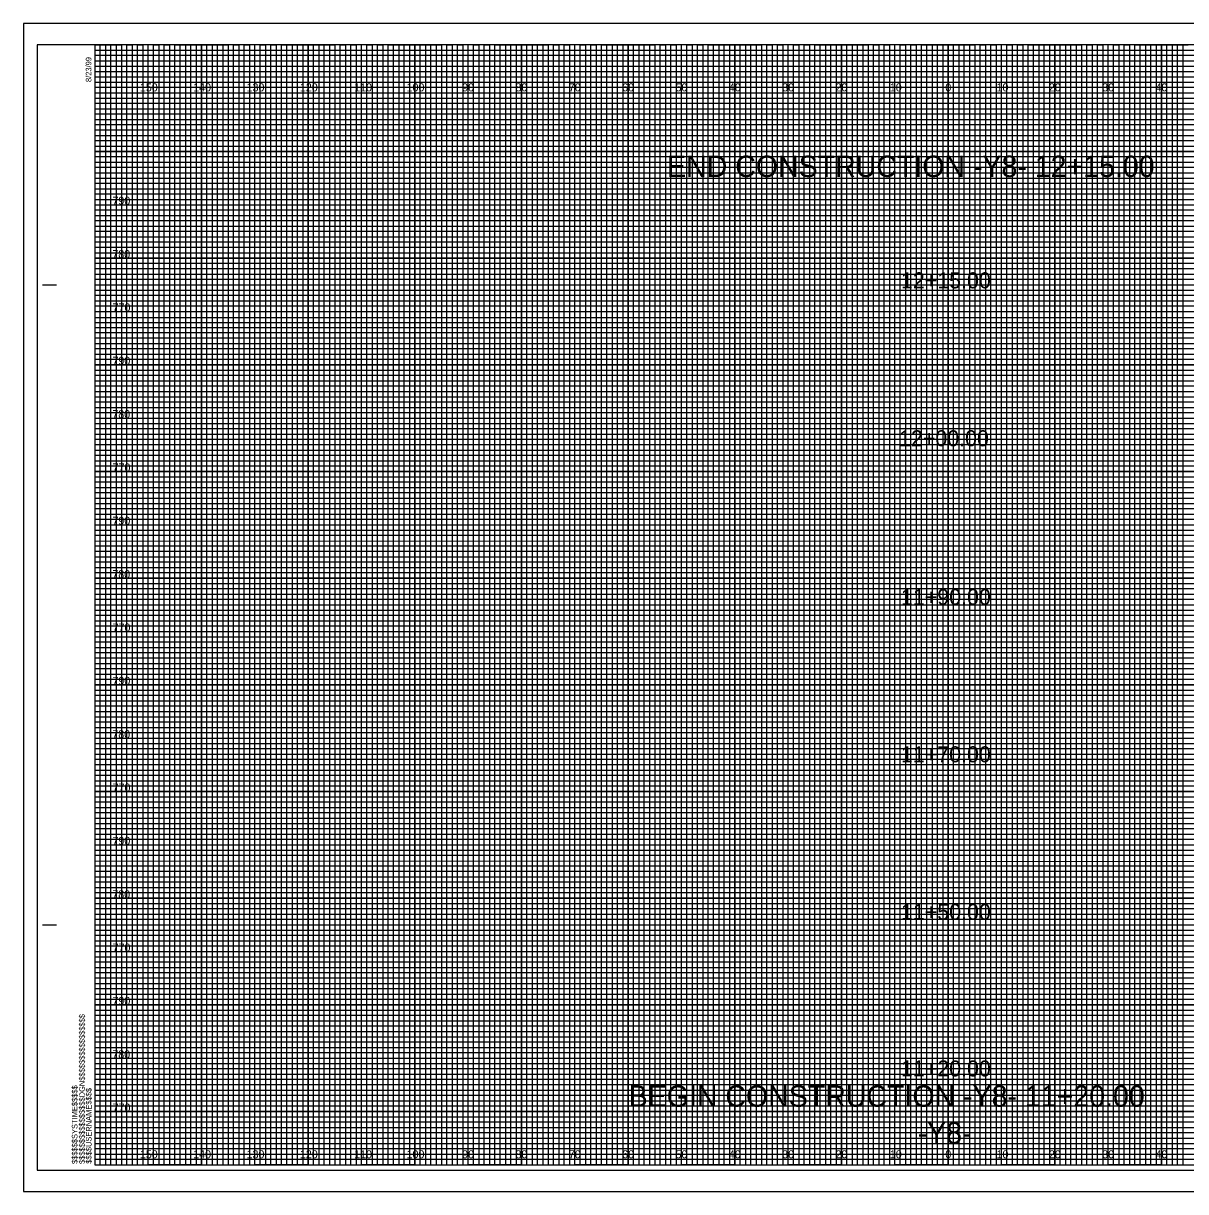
# Model space of a CAD drawing. Extents: x -13 to 323, y -5 to 214.
# Drawn here: x -13.4 to 204.5, y -5 to 214 of the extents above; entities that cross this region are included whole.
import ezdxf

# ---------------------------------------------------------------- set-up
doc = ezdxf.new("R2010")
doc.units = 0
for name, color, linetype in [('Prop XS Alignment Label', 7, 'Continuous'), ('Prop XS Elevation Labels', 7, 'Continuous'), ('Prop XS Offset Labels', 7, 'Continuous'), ('Prop XS Station Labels', 7, 'Continuous'), ('Sheet Cross Section CELL', 7, 'Continuous'), ('Sheet Cross Section Grid Major CELL', 7, 'Continuous'), ('Sheet Cross Section Grid Middle CELL', 7, 'Continuous'), ('Sheet Cross Section Grid Minor 1 CELL', 7, 'Continuous'), ('Sheet Cross Section Grid Minor 2 CELL', 7, 'Continuous'), ('Sheet Cutting Line CELL', 7, 'Continuous'), ('Sheet DOT Grid CELL', 7, 'Continuous'), ('Sheet Plot Border Inside CELL', 7, 'Continuous'), ('Sheet Plot Border Outside CELL', 7, 'Continuous')]:
    doc.layers.add(name, color=color, linetype=linetype)

msp = doc.modelspace()

# ---------------------------------------------------------------- linework, layer by layer
at = {"layer": 'Sheet Cross Section CELL'}
for p, q in [((-9.8, 165), (-7.3, 165)), ((-9.7, 165), (-7.2, 165)), ((-9.8, 45), (-7.3, 45)), ((-9.7, 45), (-7.2, 45)), ((0, 0), (0, 0)), ((0, 0), (0, 0)), ((0, 0), (0, 0)), ((0, 0), (0, 0)), ((0, 0), (0, 0)), ((0, 0), (0, 0)), ((0, 0), (0, 0))]:
    msp.add_line(p, q, dxfattribs=at)
msp.add_lwpolyline([(320, 210), (0, 210), (0, 0), (320, 0)], close=True, dxfattribs=at)
at = {"layer": 'Sheet Cross Section Grid Major CELL'}
for p, q in [((10, 210), (0, 210)), ((10, 0), (10, 210)), ((30, 210), (20, 210)), ((20, 210), (20, 0)), ((30, 0), (30, 210)), ((50, 210), (40, 210)), ((40, 210), (40, 0)), ((50, 0), (50, 210)), ((70, 210), (60, 210)), ((60, 210), (60, 0)), ((70, 0), (70, 210)), ((90, 210), (80, 210)), ((80, 210), (80, 0)), ((90, 0), (90, 210)), ((110, 210), (100, 210)), ((100, 210), (100, 0)), ((110, 0), (110, 210)), ((130, 210), (120, 210)), ((120, 210), (120, 0)), ((130, 0), (130, 210)), ((150, 210), (140, 210)), ((140, 210), (140, 0)), ((150, 0), (150, 210)), ((170, 210), (160, 210)), ((160, 210), (160, 0)), ((170, 0), (170, 210)), ((190, 210), (180, 210)), ((180, 210), (180, 0)), ((190, 0), (190, 210)), ((210, 210), (200, 210)), ((200, 210), (200, 0)), ((20, 0), (10, 0)), ((40, 0), (30, 0)), ((60, 0), (50, 0)), ((80, 0), (70, 0)), ((100, 0), (90, 0)), ((120, 0), (110, 0)), ((140, 0), (130, 0)), ((160, 0), (150, 0)), ((180, 0), (170, 0)), ((200, 0), (190, 0))]:
    msp.add_line(p, q, dxfattribs=at)
for points in [[(0, 200), (320, 200), (320, 190), (0, 190)], [(0, 180), (320, 180), (320, 170), (0, 170)], [(0, 160), (320, 160), (320, 150), (0, 150)], [(0, 140), (320, 140), (320, 130), (0, 130)], [(0, 120), (320, 120), (320, 110), (0, 110)], [(0, 100), (320, 100), (320, 90), (0, 90)], [(0, 80), (320, 80), (320, 70), (0, 70)], [(0, 60), (320, 60), (320, 50), (0, 50)], [(0, 40), (320, 40), (320, 30), (0, 30)], [(0, 20), (320, 20), (320, 10), (0, 10)]]:
    msp.add_lwpolyline(points, dxfattribs=at)
at = {"layer": 'Sheet Cross Section Grid Middle CELL'}
for points in [[(0, 210), (5, 210), (5, 0), (15, 0), (15, 210), (25, 210), (25, 0), (35, 0), (35, 210), (45, 210), (45, 0), (55, 0), (55, 210), (65, 210), (65, 0), (75, 0), (75, 210), (85, 210), (85, 0), (95, 0), (95, 210), (105, 210), (105, 0), (115, 0), (115, 210), (125, 210), (125, 0), (135, 0), (135, 210), (145, 210), (145, 0), (155, 0), (155, 210), (165, 210), (165, 0), (175, 0), (175, 210), (185, 210), (185, 0), (195, 0), (195, 210), (205, 210)], [(0, 205), (275, 205)], [(0, 185), (320, 185), (320, 195), (0, 195)], [(0, 165), (320, 165), (320, 175), (0, 175)], [(0, 145), (320, 145), (320, 155), (0, 155)], [(0, 125), (320, 125), (320, 135), (0, 135)], [(0, 105), (320, 105), (320, 115), (0, 115)], [(0, 85), (320, 85), (320, 95), (0, 95)], [(0, 65), (320, 65), (320, 75), (0, 75)], [(0, 45), (320, 45), (320, 55), (0, 55)], [(0, 25), (320, 25), (320, 35), (0, 35)], [(0, 5), (320, 5), (320, 15), (0, 15)]]:
    msp.add_lwpolyline(points, dxfattribs=at)
at = {"layer": 'Sheet Cross Section Grid Minor 1 CELL'}
for p, q in [((0, 209), (260, 209)), ((260, 207.98), (0, 207.98)), ((0, 207.98), (0, 207)), ((0, 207), (260, 207)), ((260, 205.89), (0, 205.89)), ((0, 205.89), (0, 204)), ((0, 204), (320, 204))]:
    msp.add_line(p, q, dxfattribs=at)
for points in [[(0, 203), (270, 203), (320, 203), (320, 202), (0, 202)], [(0, 201), (320, 201), (320, 199), (0, 199)], [(0, 198), (320, 198), (320, 197), (0, 196.98)], [(0, 196), (320, 196), (320, 194), (0, 194)], [(0, 193), (320, 193), (320, 192), (0, 192)], [(0, 191), (320, 191), (320, 189), (0, 189)], [(0, 188), (320, 188), (320, 187), (0, 187)], [(0, 186), (320, 186), (320, 184), (0, 184)], [(0, 183), (320, 183), (320, 182), (0, 182)], [(0, 181), (320, 181), (320, 179), (0, 179)], [(0, 178), (320, 178), (320, 177), (0, 177)], [(0, 176), (320, 176), (320, 173.95), (320, 173), (320, 172), (0, 172)], [(0, 174), (320, 174), (320, 173), (0, 173)], [(0, 171), (320, 171), (320, 169), (0, 169.03)], [(0, 169.03), (320, 169), (320, 168), (0, 168)], [(0, 167), (320, 167), (320, 166), (0, 166)], [(0, 164), (320, 164), (320, 163), (0, 163)], [(0, 162), (320, 162), (320, 161), (0, 161)], [(-0.07, 158.89), (320, 158.89), (320, 157.88), (-0.07, 157.88)], [(0, 157), (320, 157), (320, 156), (0, 156)], [(0, 154), (320, 154), (320, 153), (0, 153)], [(0, 152), (320, 152), (320, 151), (0, 151)], [(0, 149), (320, 149), (320, 148), (0, 148)], [(0, 147), (320, 147), (320, 146), (0, 146)], [(0, 144), (320, 144), (320, 143), (0, 143)], [(0, 142), (320, 142), (320, 141), (0, 141)], [(0, 139), (320, 139), (319.99, 137.98), (0, 138)], [(0, 137), (320, 137), (320, 136), (0, 136)], [(0, 134), (320, 134), (320, 133), (0, 133)], [(0, 132), (320, 132), (320, 131), (0, 131)], [(0, 129), (320, 129), (320, 128), (0, 128)], [(0, 127), (320, 127), (320, 126), (0, 126)], [(0, 124), (320, 124), (320, 123), (0, 123)], [(0, 122), (320, 122), (320, 121), (0, 121)], [(0, 119), (320, 119), (320, 118), (0, 118)], [(0, 116.99), (320.07, 116.91), (320, 116), (0, 116)], [(0, 114), (320, 114), (320, 113), (0, 113)], [(0, 112), (320, 112), (320, 111), (0, 111)], [(0, 109), (320, 109), (320, 108), (0, 108)], [(0, 107), (320, 107), (320, 106), (0, 106)], [(0, 104), (320, 104), (320, 103), (0, 103)], [(0, 102), (320, 102), (320, 101), (0, 101)], [(0, 99), (320, 99), (320, 98), (0, 98)], [(0, 97), (320, 97), (320, 96), (0, 96)], [(0, 94), (320, 94), (320, 93), (0, 93)], [(0, 92), (320, 92), (320, 91), (0, 91)], [(0, 89), (320, 89), (320, 88), (0, 88)], [(0, 87), (320, 87), (320, 86), (0, 86)], [(0, 84), (320, 84), (320, 83), (0, 83)], [(0, 82), (320, 82), (320, 81), (0, 81)], [(0, 79), (320, 79), (319.99, 77.98), (0, 78)], [(0, 77), (320, 77), (320, 76), (0, 76)], [(0, 74), (320, 74), (320, 73), (0, 73)], [(0, 72), (320, 72), (320, 71), (0, 71)], [(0, 69), (320, 69), (320, 68), (0, 68)], [(0, 67), (320, 67), (320, 66), (0, 66)], [(0, 64), (320, 64), (320, 63), (0, 63)], [(0, 62), (320, 62), (320, 61), (0, 61)], [(0, 59), (320, 59), (320, 58), (0, 58)], [(0, 56.99), (320.07, 56.91), (320, 56), (0, 56)], [(0, 54), (320, 54), (320, 53), (0, 53)], [(0, 52), (320, 52), (320, 51), (0, 51)], [(0, 49), (320, 49), (320, 48), (0, 48)], [(0, 47), (320, 47), (320, 46), (0, 46)], [(0, 44), (320, 44), (320, 43), (0, 43)], [(0, 42), (320, 42), (320, 41), (0, 41)], [(0, 39), (320, 39), (320, 38), (0, 38)], [(0, 37), (320, 37), (320, 36), (0, 36)], [(0, 34), (320, 34), (320, 33), (0, 33)], [(0, 32), (320, 32), (320, 31), (0, 31)], [(0, 29), (320, 29), (320, 28), (0, 28)], [(0, 27), (320, 27), (320, 26), (0, 26)], [(0, 24), (320, 24), (320, 23), (0, 23)], [(0, 22), (320, 22), (320, 21), (0, 21)], [(0, 19), (320, 19), (320, 18), (0, 18)], [(0, 17), (320, 17), (320, 16), (0, 16)], [(0, 14), (320, 14), (320, 13), (0, 13)], [(0, 12), (320, 12), (320, 11), (0, 11)], [(0, 9), (320, 9), (320, 8), (0, 8)], [(0, 7), (320, 7), (320, 6), (0, 6)], [(0, 4), (320, 4), (320, 3), (0, 3)], [(0, 2), (320, 2), (320, 1), (0, 1)]]:
    msp.add_lwpolyline(points, dxfattribs=at)
at = {"layer": 'Sheet Cross Section Grid Minor 2 CELL'}
for points in [[(0, 0), (1, 0), (1, 210), (2, 210), (2, 0)], [(2, 0), (3, 0), (3, 210), (4, 210), (4, 0)], [(5, 0), (6, 0), (6, 210), (7, 210), (7, 0)], [(7, 0), (8, 0), (8, 210), (9, 210), (9, 0)], [(10, 0), (11, 0), (11, 210), (12, 210), (12, 0)], [(12, 0), (13, 0), (13, 210), (14, 210), (14, 0)], [(15, 0), (16, 0), (16, 210), (17, 210), (17, 0)], [(17, 0), (18, 0), (18, 210), (19, 210), (19, 0)], [(20, 0), (21, 0), (21, 210), (22, 210), (22, 0)], [(22, 0), (23, 0), (23, 210), (24, 210), (24, 0)], [(25, 0), (26, 0), (26, 210), (27, 210), (27, 0)], [(27, 0), (28, 0), (28, 210), (29, 210), (29, 0)], [(30, 0), (31, 0), (31, 210), (32, 210), (32, 0)], [(32, 0), (33, 0), (33, 210), (34, 210), (34, 0)], [(35, 0), (36, 0), (36, 210), (37, 210), (37, 0)], [(37, 0), (38, 0), (38, 210), (39, 210), (39, 0)], [(40, 0), (41, 0), (41, 210), (42, 210), (42, 0)], [(42, 0), (43, 0), (43, 210), (44, 210), (44, 0)], [(45, 0), (46, 0), (46, 210), (47, 210), (47, 0)], [(47, 0), (48, 0), (48, 210), (49, 210), (49, 0)], [(50, 0), (51, 0), (51, 210), (52, 210), (52, 0)], [(52, 0), (53, 0), (53, 210), (54, 210), (54, 0)], [(55, 0), (56, 0), (56, 210), (57, 210), (57, 0)], [(57, 0), (58, 0), (58, 210), (59, 210), (59, 0)], [(60, 0), (61, 0), (61, 210), (62, 210), (62, 0)], [(62, 0), (63, 0), (63, 210), (64, 210), (64, 0)], [(65, 0), (66, 0), (66, 210), (67, 210), (67, 0)], [(67, 0), (68, 0), (68, 210), (69, 210), (69, 0)], [(70, 0), (71, 0), (71, 210), (72, 210), (72, 0)], [(72, 0), (73, 0), (73, 210), (74, 210), (74, 0)], [(75, 0), (76, 0), (76, 210), (77, 210), (77, 0)], [(77, 0), (78, 0), (78, 210), (79, 210), (79, 0)], [(80, 0), (81, 0), (81, 210), (82, 210), (82, 0)], [(82, 0), (83, 0), (83, 210), (84, 210), (84, 0)], [(85, 0), (86, 0), (86, 210), (87, 210), (87, 0)], [(87, 0), (88, 0), (88, 210), (89, 210), (89, 0)], [(90, 0), (91, 0), (91, 210), (92, 210), (92, 0)], [(92, 0), (93, 0), (93, 210), (94, 210), (94, 0)], [(95, 0), (96, 0), (96, 210), (97, 210), (97, 0)], [(97, 0), (98, 0), (98, 210), (99, 210), (99, 0)], [(100, 0), (101, 0), (101, 210), (102, 210), (102, 0)], [(102, 0), (103, 0), (103, 210), (104, 210), (104, 0)], [(105, 0), (106, 0), (106, 210), (107, 210), (107, 0)], [(107, 0), (108, 0), (108, 210), (109, 210), (109, 0)], [(110, 0), (111, 0), (111, 210), (112, 210), (112, 0)], [(112, 0), (113, 0), (113, 210), (114, 210), (114, 0)], [(115, 0), (116, 0), (116, 210), (117, 210), (117, 0)], [(117, 0), (118, 0), (118, 210), (119, 210), (119, 0)], [(120, 0), (121, 0), (121, 210), (122, 210), (122, 0)], [(122, 0), (123, 0), (123, 210), (124, 210), (124, 0)], [(125, 0), (126, 0), (126, 210), (127, 210), (127, 0)], [(127, 0), (128, 0), (128, 210), (129, 210), (129, 0)], [(130, 0), (131, 0), (131, 210), (132, 210), (132, 0)], [(132, 0), (133, 0), (133, 210), (134, 210), (134, 0)], [(135, 0), (136, 0), (136, 210), (137, 210), (137, 0)], [(137, 0), (138, 0), (138, 210), (139, 210), (139, 0)], [(140, 0), (141, 0), (141, 210), (142, 210), (142, 0)], [(142, 0), (143, 0), (143, 210), (144, 210), (144, 0)], [(145, 0), (146, 0), (146, 210), (147, 210), (147, 0)], [(147, 0), (148, 0), (148, 210), (149, 210), (149, 0)], [(150, 0), (151, 0), (151, 210), (152, 210), (152, 0)], [(152, 0), (153, 0), (153, 210), (154, 210), (154, 0)], [(155, 0), (156, 0), (156, 210), (157, 210), (157, 0)], [(157, 0), (158, 0), (158, 210), (159, 210), (159, 0)], [(160, 0), (161, 0), (161, 210), (162, 210), (162, 0)], [(162, 0), (163, 0), (163, 210), (164, 210), (164, 0)], [(165, 0), (166, 0), (166, 210), (167, 210), (167, 0)], [(167, 0), (168, 0), (168, 210), (169, 210), (169, 0)], [(170, 0), (171, 0), (171, 210), (172, 210), (172, 0)], [(172, 0), (173, 0), (173, 210), (174, 210), (174, 0)], [(175, 0), (176, 0), (176, 210), (177, 210), (177, 0)], [(177, 0), (178, 0), (178, 210), (179, 210), (179, 0)], [(180, 0), (181, 0), (181, 210), (182, 210), (182, 0)], [(182, 0), (183, 0), (183, 210), (184, 210), (184, 0)], [(185, 0), (186, 0), (186, 210), (187, 210), (187, 0)], [(187, 0), (188, 0), (188, 210), (189, 210), (189, 0)], [(190, 0), (191, 0), (191, 210), (192, 210), (192, 0)], [(192, 0), (193, 0), (193, 210), (194, 210), (194, 0)], [(195, 0), (196, 0), (196, 210), (197, 210), (197, 0)], [(197, 0), (198, 0), (198, 210), (199, 210), (199, 0)], [(200, 0), (201, 0), (201, 210), (202, 210), (202, 0)], [(202, 0), (203, 0), (203, 210), (204, 210), (204, 0)]]:
    msp.add_lwpolyline(points, dxfattribs=at)
at = {"layer": 'Sheet Cutting Line CELL'}
for p, q in [((323.3, 214), (-13.4, 214)), ((-13.4, 214), (-13.4, -5)), ((-13.4, -5), (323.3, -5))]:
    msp.add_line(p, q, dxfattribs=at)
at = {"layer": 'Sheet DOT Grid CELL'}
for p, q in [((10, 0), (10, 210)), ((20, 0), (20, 210)), ((30, 0), (30, 210)), ((40, 0), (40, 210)), ((50, 0), (50, 210)), ((60, 0), (60, 210)), ((70, 0), (70, 210)), ((80, 0), (80, 210)), ((90, 0), (90, 210)), ((100, 0), (100, 210)), ((110, 0), (110, 210)), ((120, 0), (120, 210)), ((130, 0), (130, 210)), ((140, 0), (140, 210)), ((150, 0), (150, 210)), ((160, 0), (160, 210)), ((170, 0), (170, 210)), ((180, 0), (180, 210)), ((190, 0), (190, 210)), ((200, 0), (200, 210)), ((0, 200), (320, 200)), ((0, 190), (320, 190)), ((0, 180), (320, 180)), ((0, 170), (320, 170)), ((0, 160), (320, 160)), ((0, 150), (320, 150)), ((0, 140), (320, 140)), ((0, 130), (320, 130)), ((0, 120), (320, 120)), ((0, 110), (320, 110)), ((0, 100), (320, 100)), ((0, 90), (320, 90)), ((0, 80), (320, 80)), ((0, 70), (320, 70)), ((0, 60), (320, 60)), ((0, 50), (320, 50)), ((0, 40), (320, 40)), ((0, 30), (320, 30)), ((0, 20), (320, 20)), ((0, 10), (320, 10))]:
    msp.add_line(p, q, dxfattribs=at)
at = {"layer": 'Sheet Plot Border Inside CELL'}
msp.add_lwpolyline([(-10.8, -1), (322.4, -1), (322.4, 210), (-10.8, 210)], close=True, dxfattribs=at)
at = {"layer": 'Sheet Plot Border Outside CELL'}
msp.add_lwpolyline([(-13.4, -5), (323.3, -5), (323.3, 214), (-13.4, 214)], close=True, dxfattribs=at)

# ---------------------------------------------------------------- texts
at = {"layer": 'Prop XS Alignment Label'}
for s, p in [('END CONSTRUCTION -Y8- 12+15.00', (107.28, 185.2)), ('BEGIN CONSTRUCTION -Y8- 11+20.00', (100.08, 10.91)), ('-Y8-', (154.25, 4))]:
    msp.add_text(s, height=4, dxfattribs=at).set_placement(p)
at = {"layer": 'Prop XS Elevation Labels'}
for s, p in [('790', (3.3, 180)), ('780', (3.28, 170)), ('770', (3.33, 160)), ('790', (3.3, 150)), ('780', (3.28, 140)), ('770', (3.33, 130)), ('790', (3.3, 120)), ('780', (3.28, 110)), ('770', (3.33, 100)), ('790', (3.3, 90)), ('780', (3.28, 80)), ('770', (3.33, 70)), ('790', (3.3, 60)), ('780', (3.28, 50)), ('770', (3.33, 40)), ('790', (3.3, 30)), ('780', (3.28, 20)), ('770', (3.33, 10))]:
    msp.add_text(s, height=1.5, dxfattribs=at).set_placement(p)
at = {"layer": 'Prop XS Offset Labels'}
for s, p in [('150', (8.44, 201.25)), ('140', (18.44, 201.25)), ('130', (28.44, 201.25)), ('120', (38.44, 201.25)), ('110', (48.62, 201.25)), ('100', (58.44, 201.25)), ('90', (68.86, 201.25)), ('80', (78.86, 201.25)), ('70', (88.86, 201.25)), ('60', (98.86, 201.25)), ('50', (108.86, 201.25)), ('40', (118.86, 201.25)), ('30', (128.86, 201.25)), ('20', (138.86, 201.25)), ('10', (149.04, 201.25)), ('0', (159.45, 201.25)), ('0', (159.45, 201.25)), ('10', (169.04, 201.25)), ('20', (178.86, 201.25)), ('30', (188.86, 201.25)), ('40', (198.86, 201.25)), ('150', (8.44, 1.25)), ('140', (18.44, 1.25)), ('130', (28.44, 1.25)), ('120', (38.44, 1.25)), ('110', (48.62, 1.25)), ('100', (58.44, 1.25)), ('90', (68.86, 1.25)), ('80', (78.86, 1.25)), ('70', (88.86, 1.25)), ('60', (98.86, 1.25)), ('50', (108.86, 1.25)), ('40', (118.86, 1.25)), ('30', (128.86, 1.25)), ('20', (138.86, 1.25)), ('10', (149.04, 1.25)), ('0', (159.45, 1.25)), ('0', (159.45, 1.25)), ('10', (169.04, 1.25)), ('20', (178.86, 1.25)), ('30', (188.86, 1.25)), ('40', (198.86, 1.25))]:
    msp.add_text(s, height=1.5, dxfattribs=at).set_placement(p)
at = {"layer": 'Prop XS Station Labels'}
for s, p in [('12+15.00', (151.13, 164.33)), ('12+00.00', (150.77, 134.72)), ('11+90.00', (151.13, 104.98)), ('11+70.00', (151.13, 75.48)), ('11+50.00', (151.13, 45.94)), ('11+20.00', (151.13, 16.59))]:
    msp.add_text(s, height=3, dxfattribs=at).set_placement(p)
at = {"layer": 'Sheet Cross Section CELL'}
for s, p in [('8/23/99', (-0.65, 203)), ('$$$$$$$$$$$$$$$$DGN$$$$$$$$$$$$$$$$', (-1.88, 0.18)), ('$$$$$$SYSTIME$$$$$', (-3.26, 0.18)), ('$$$$USERNAME$$$$', (-0.62, 0.23))]:
    msp.add_text(s, height=1.05, rotation=90, dxfattribs=at).set_placement(p)

doc.saveas('drawing.dxf')
